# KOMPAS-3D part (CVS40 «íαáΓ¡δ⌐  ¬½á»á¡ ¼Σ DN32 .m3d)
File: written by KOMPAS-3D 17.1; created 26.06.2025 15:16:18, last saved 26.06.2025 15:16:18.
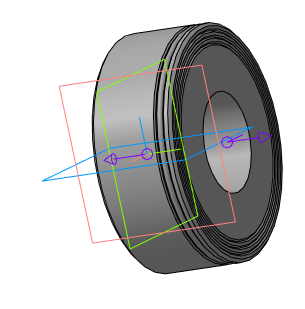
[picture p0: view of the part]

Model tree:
1. Эскиз:1
2. Элемент вращения:1
     Угол 1 = 360
3. Присоединительная точка:1
4. Присоединительная точка:2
